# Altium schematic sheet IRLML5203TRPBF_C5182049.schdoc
size 127 x 101 mm
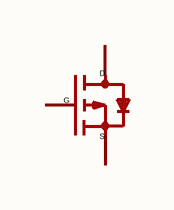
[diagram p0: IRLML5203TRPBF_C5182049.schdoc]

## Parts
Q?  irlml5203trpbf_c5182049  [SOT-23-3_L2.9-W1.3-P1.90-LS2.4-BR]  (value not drawn)

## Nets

Not connected (* = marked no-connect by the designer): Q? 1(G) 2(S) 3(D)

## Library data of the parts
Q? = irlml5203trpbf_c5182049: 漏源电压(Vdss):30V;连续漏极电流(Id):3A;导通电阻(RDS(on)):75mΩ@4.5V,2A;耗散功率(Pd):1.25W;阈值电压(Vgs(th)):3V;; Manufacturer: TECH PUBLIC(台舟); AddInBom: yes; ModelId: c62791f0466c4ae2a892c056b845b0ca; ModelName: SOT-23-3P_L2.9-W1.3-H1.0-LS2.4-P0.95; ModelTransform: 98.425,114.173,0,180,0,0,0.0005,-0.0005,0; Drain to Source Voltage: 30V; Current - Continuous Drain(Id): 3A; Pd - Power Dissipation: 1.25W; Gate Threshold Voltage (Vgs(th)): 3V; Gate Charge(Qg): 10nC@10V; Input Capacitance(Ciss): 565pF@30V; Reverse Transfer Capacitance (Crss@Vds): 75pF; Output Capacitance(Coss): 126pF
